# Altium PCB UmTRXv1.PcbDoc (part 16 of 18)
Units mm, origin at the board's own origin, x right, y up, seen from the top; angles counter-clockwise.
Board outline 172 x 113 mm, 6 copper layers (Top Layer, GND, MidLayer1, Mid-Layer 2, InternalPlane2, Bottom Layer); 766 components, 613 nets, 3008 pads, 1360 vias.
Unrouted connection lines stored in the file: 2.
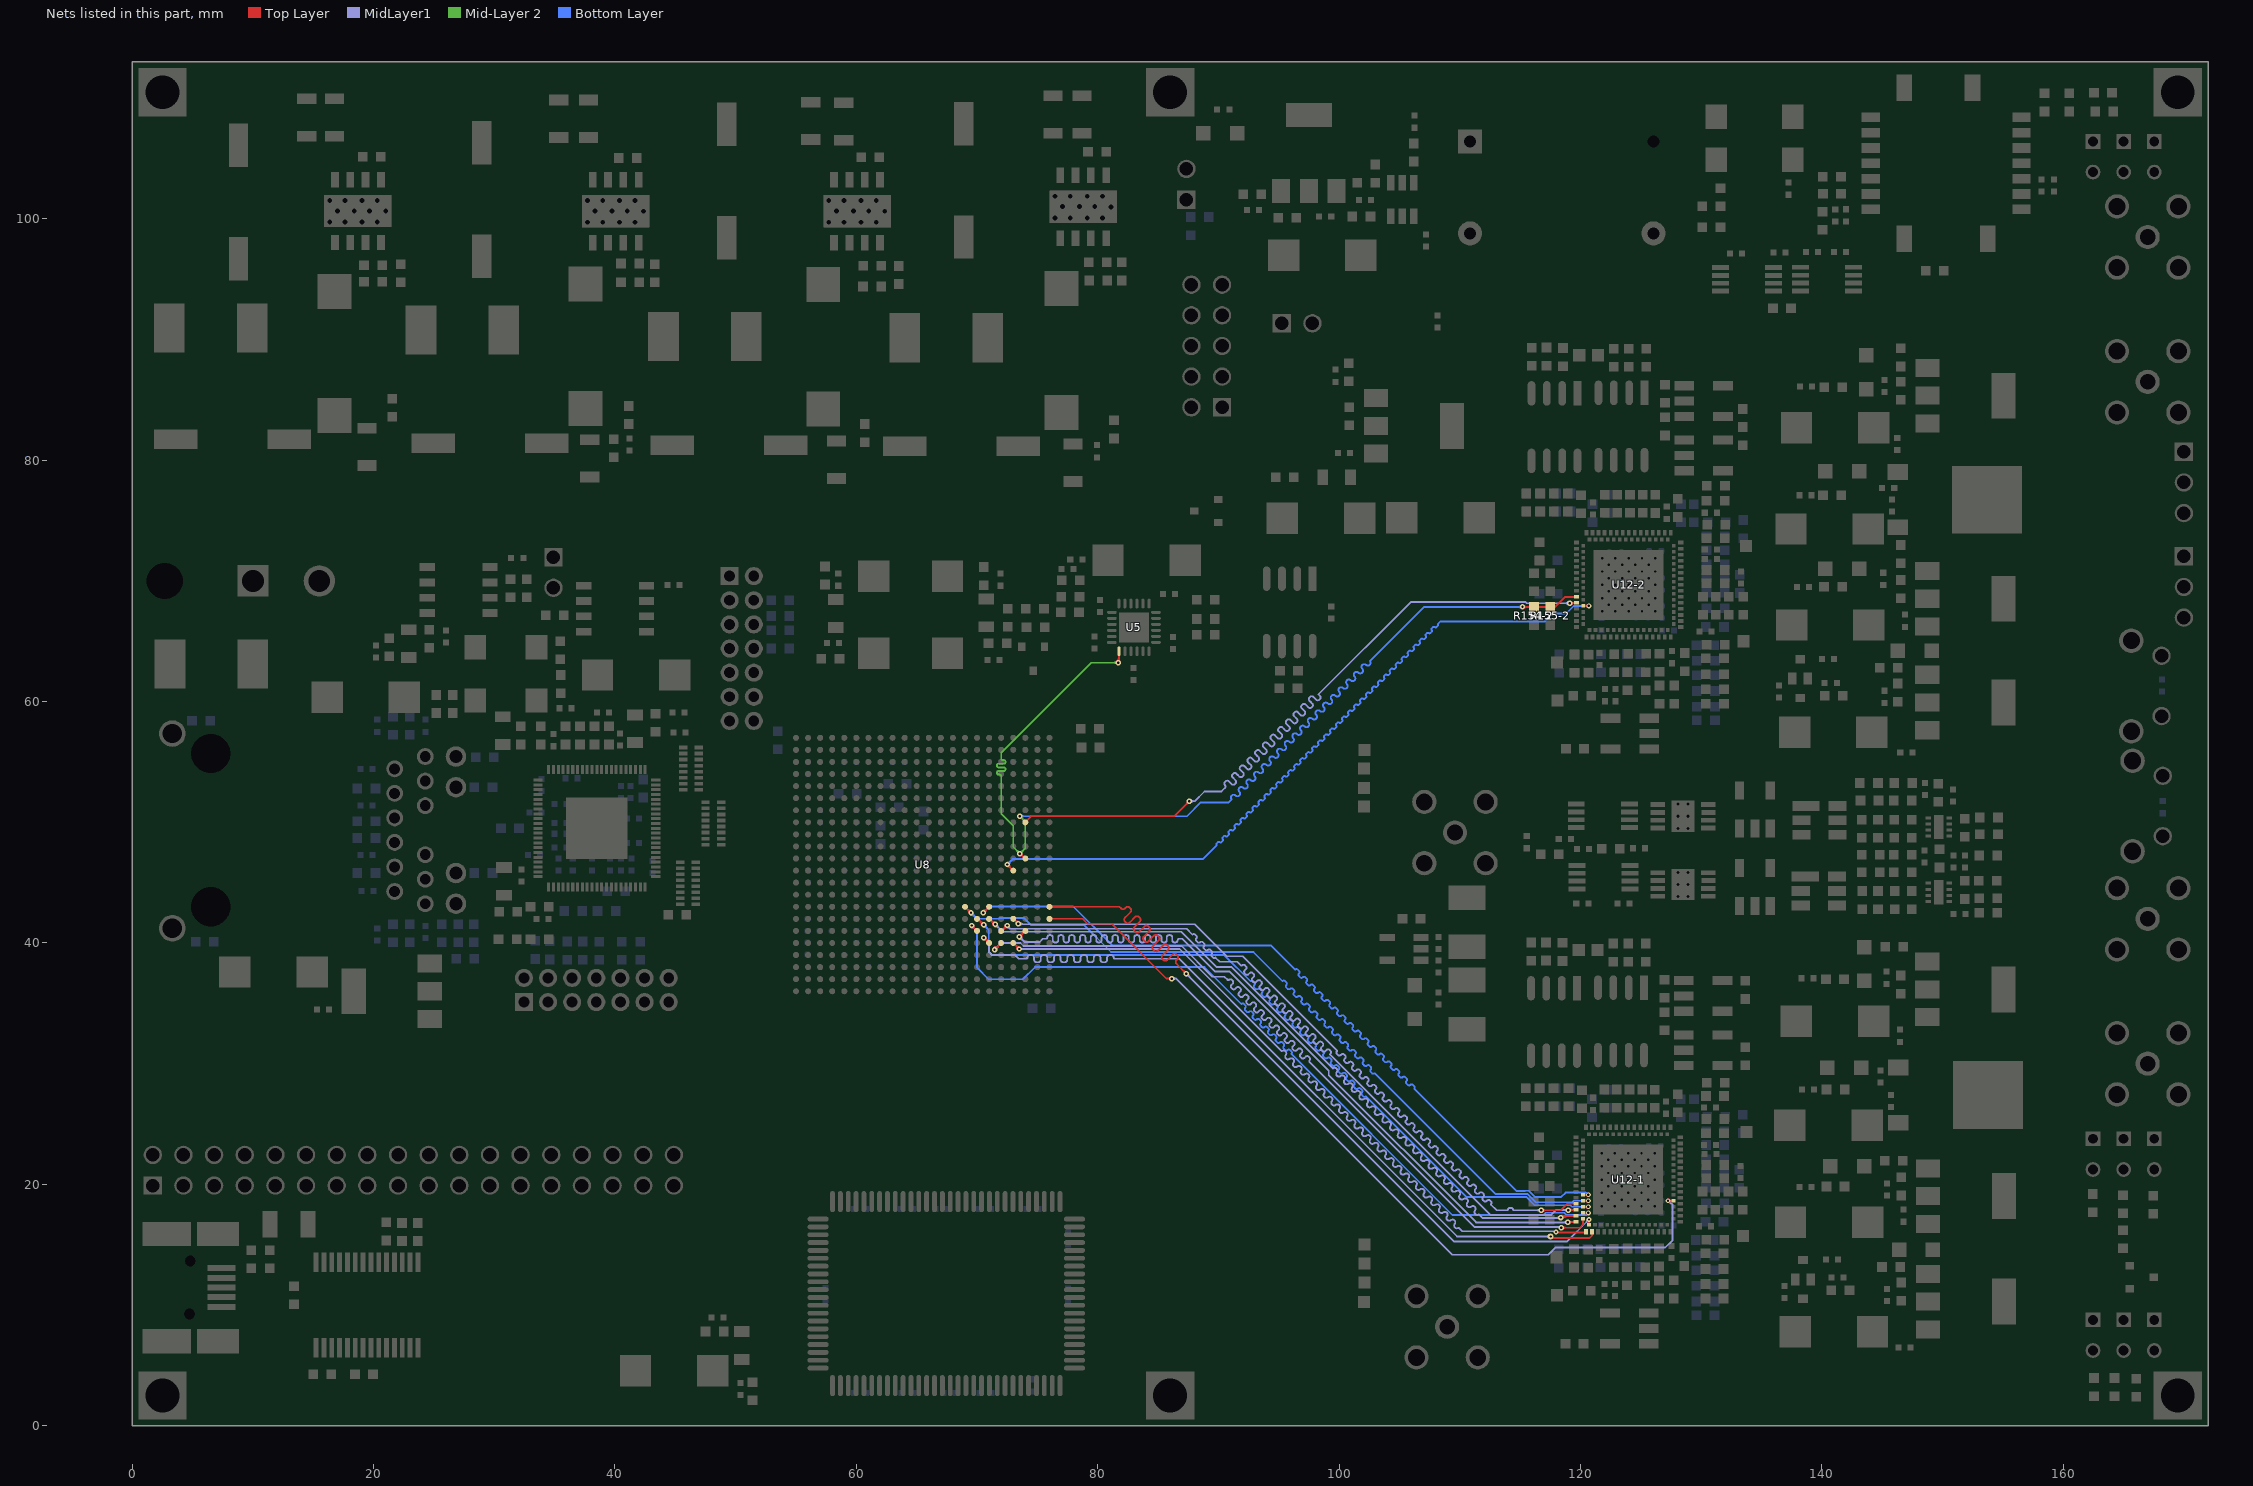
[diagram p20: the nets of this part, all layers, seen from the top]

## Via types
v1: diameter 0.45, hole 0.2, Top Layer to Bottom Layer, tented both sides, 554 vias
v2: diameter 0.5, hole 0.2, Top Layer to Bottom Layer, tented both sides, 468 vias
v3: diameter 0.7, hole 0.3, Top Layer to Bottom Layer, tented both sides, 206 vias
v4: diameter 0.4, hole 0.2, Top Layer to Bottom Layer, tented both sides, 82 vias
v5: diameter 0.8, hole 0.3, Top Layer to Bottom Layer, tented both sides, 16 vias
v6: diameter 0.6, hole 0.25, Top Layer to Bottom Layer, tented both sides, 16 vias
v7: diameter 0.5, hole 0.3, Top Layer to Bottom Layer, tented both sides, 8 vias
v8: diameter 0.7, hole 0.3, Top Layer to Bottom Layer, 4 vias
v9: diameter 0.6, hole 0.3, Top Layer to Bottom Layer, tented both sides, 4 vias
v10: diameter 0.5, hole 0.2, Top Layer to Bottom Layer, 2 vias

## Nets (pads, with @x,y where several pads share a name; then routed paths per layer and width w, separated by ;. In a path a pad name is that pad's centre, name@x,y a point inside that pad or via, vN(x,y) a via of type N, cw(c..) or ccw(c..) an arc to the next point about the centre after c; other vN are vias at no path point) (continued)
TX1D1: U8.H8 U12-1.22 | length 68.6
  Top Layer w0.15: U8.H8@69,43 v1(69.5,42.5) ; v1@69.325,42.5 ccw(c68.903,42.5) 69.201,42.799 ccw(c69.5,43.098) v1@69.5,42.675
  Top Layer w0.2: U12-1.22@120.207,18.638 v4@120.632,18.638 ; v4@120.586,18.567 ccw(c120.416,18.397) 120.416,18.638 ccw(c120.416,18.879) v4@120.586,18.709
  Bottom Layer w0.15: v1@69.5,42.325 cw(c69.5,41.903) 69.799,42.201 cw(c70.097,42.5) v1@69.675,42.5 ; v1(69.5,42.5) 70,42 71.8,42 71.875,42.075 73.875,42.075 74.45,41.5 78.85,41.5 81.1,39.25 92.9,39.25 95.309,36.841 cw(c95.415,36.735) 95.521,36.841 95.627,36.735 cw(c95.521,36.629) 95.627,36.523 ccw(c95.733,36.417) 95.627,36.311 95.733,36.205 ccw(c95.839,36.311) 95.945,36.205 cw(c96.052,36.098) 96.158,36.205 96.264,36.098 cw(c96.158,35.992) 96.264,35.886 ccw(c96.37,35.78) 96.264,35.674 96.37,35.568 ccw(c96.476,35.674) 96.582,35.568 cw(c96.688,35.462) 96.794,35.568 96.9,35.462 cw(c96.794,35.356) 96.9,35.25 ccw(c97.006,35.144) 96.9,35.038 97.006,34.932 ccw(c97.112,35.038) 97.218,34.932 cw(c97.324,34.826) 97.43,34.932 97.536,34.826 cw(c97.43,34.72) 97.536,34.614 ccw(c97.643,34.507) 97.536,34.401 97.643,34.295 ccw(c97.749,34.401) 97.855,34.295 cw(c97.961,34.189) 98.067,34.295 98.173,34.189 cw(c98.067,34.083) 98.173,33.977 ccw(c98.279,33.871) 98.173,33.765 98.279,33.659 ccw(c98.385,33.765) 98.491,33.659 cw(c98.597,33.553) 98.703,33.659 98.809,33.553 cw(c98.703,33.447) 98.809,33.341 ccw(c98.915,33.235) 98.809,33.129 98.915,33.023 ccw(c99.021,33.129) 99.127,33.023 cw(c99.234,32.916) 99.34,33.023 99.446,32.916 cw(c99.34,32.81) 99.446,32.704 ccw(c99.552,32.598) 99.446,32.492 99.552,32.386 ccw(c99.658,32.492) 99.764,32.386 cw(c99.87,32.28) 99.976,32.386 100.082,32.28 cw(c99.976,32.174) 100.082,32.068 ccw(c100.188,31.962) 100.082,31.856 100.188,31.75 ccw(c100.294,31.856) 100.4,31.75 cw(c100.506,31.644) 100.612,31.75 100.718,31.644 cw(c100.612,31.538) 100.718,31.432 ccw(c100.825,31.325) 100.718,31.219 100.825,31.113 ccw(c100.931,31.219) 101.037,31.113 cw(c101.143,31.007) 101.249,31.113 101.355,31.007 cw(c101.249,30.901) 101.355,30.795 ccw(c101.461,30.689) 101.355,30.583 101.461,30.477 ccw(c101.567,30.583) 101.673,30.477 cw(c101.779,30.371) 101.885,30.477 101.991,30.371 cw(c101.885,30.265) 101.991,30.159 ccw(c102.097,30.053) 101.991,29.947 102.097,29.841 ccw(c102.203,29.947) 102.309,29.841 cw(c102.416,29.734) 102.522,29.841 102.628,29.734 cw(c102.522,29.628) 102.628,29.522 ccw(c102.734,29.416) 102.628,29.31 102.734,29.204 ccw(c102.84,29.31) 102.946,29.204 112.942,19.208 115.53,19.208 115.544,19.222 115.596,19.222 116.298,18.52 119.31,18.52 119.428,18.638 v4(120.657,18.638) ; v4@120.569,18.55 ccw(c120.355,18.336) 120.355,18.638 ccw(c120.355,18.94) v4@120.569,18.726
TX1D2: U8.G4 U12-1.23 | length 69.6
  Top Layer w0.15: U8.G4@73,42 v1(73.4,41.6) ; v1@73.225,41.6 ccw(c72.802,41.6) 73.101,41.899 ccw(c73.4,42.197) v1@73.4,41.775 ; v1(116.75,17.85) 118.35,17.85 118.888,18.388 U12-1.23@119.632,18.388 ; v1@116.856,17.744 cw(c117.112,17.488) 117.112,17.85 cw(c117.112,18.212) v1@116.856,17.956 ; v1(73.4,41.6) 73.45,41.65 73.45,41.55 v1(73.4,41.6)
  MidLayer1 w0.15: v1@73.4,41.55 88.05,41.55 90.7,38.9 92,38.9 99.831,31.069 cw(c99.817,31.055) 99.831,31.041 ccw(c99.958,30.914) 99.831,30.786 99.894,30.723 ccw(c100.022,30.85) 100.149,30.723 100.163,30.737 100.177,30.751 cw(c100.304,30.624) 100.432,30.751 100.495,30.687 cw(c100.368,30.56) 100.495,30.433 100.481,30.419 100.467,30.405 ccw(c100.594,30.277) 100.467,30.15 100.531,30.086 ccw(c100.658,30.214) 100.785,30.086 100.799,30.101 100.814,30.115 cw(c100.941,29.987) 101.068,30.115 101.132,30.051 cw(c101.004,29.924) 101.132,29.797 101.118,29.782 101.103,29.768 ccw(c101.231,29.641) 101.103,29.514 101.167,29.45 ccw(c101.294,29.577) 101.422,29.45 101.436,29.464 101.45,29.478 cw(c101.577,29.351) 101.704,29.478 101.768,29.415 cw(c101.641,29.287) 101.768,29.16 101.74,29.132 ccw(c101.867,29.005) 101.74,28.877 101.803,28.814 ccw(c101.931,28.941) 102.058,28.814 102.072,28.828 102.086,28.842 cw(c102.214,28.715) 102.341,28.842 102.405,28.778 cw(c102.277,28.651) 102.405,28.524 102.39,28.51 102.376,28.495 ccw(c102.504,28.368) 102.376,28.241 102.44,28.177 ccw(c102.567,28.305) 102.694,28.177 102.709,28.191 102.723,28.206 cw(c102.85,28.078) 102.977,28.206 103.041,28.142 cw(c102.914,28.015) 103.041,27.887 103.027,27.873 103.013,27.859 ccw(c103.14,27.732) 103.013,27.605 103.076,27.541 ccw(c103.204,27.668) 103.331,27.541 103.345,27.555 103.359,27.569 cw(c103.486,27.442) 103.614,27.569 103.677,27.506 cw(c103.55,27.378) 103.677,27.251 103.663,27.237 103.649,27.223 ccw(c103.776,27.095) 103.649,26.968 103.713,26.904 ccw(c103.84,27.032) 103.967,26.904 103.996,26.933 cw(c104.123,26.805) 104.25,26.933 104.314,26.869 cw(c104.186,26.742) 104.314,26.615 104.3,26.6 104.285,26.586 ccw(c104.413,26.459) 104.285,26.332 104.349,26.268 ccw(c104.476,26.395) 104.604,26.268 104.618,26.282 104.632,26.296 cw(c104.759,26.169) 104.886,26.296 104.95,26.233 cw(c104.823,26.105) 104.95,25.978 104.936,25.964 104.922,25.95 ccw(c105.049,25.823) 104.922,25.695 104.985,25.632 ccw(c105.113,25.759) 105.24,25.632 105.254,25.646 105.268,25.66 cw(c105.396,25.533) 105.523,25.66 105.587,25.596 cw(c105.459,25.469) 105.587,25.342 105.572,25.328 105.558,25.313 ccw(c105.685,25.186) 105.558,25.059 105.622,24.995 ccw(c105.749,25.123) 105.876,24.995 105.891,25.009 105.905,25.024 cw(c106.032,24.896) 106.159,25.024 106.223,24.96 cw(c106.096,24.833) 106.223,24.705 106.209,24.691 106.195,24.677 ccw(c106.322,24.55) 106.195,24.423 106.258,24.359 ccw(c106.386,24.486) 106.513,24.359 106.527,24.373 106.541,24.387 cw(c106.668,24.26) 106.796,24.387 106.859,24.324 cw(c106.732,24.196) 106.859,24.069 106.845,24.055 106.831,24.041 ccw(c106.958,23.913) 106.831,23.786 106.895,23.723 ccw(c107.022,23.85) 107.149,23.723 107.163,23.737 107.177,23.751 cw(c107.305,23.624) 107.432,23.751 107.496,23.687 cw(c107.368,23.56) 107.496,23.433 107.482,23.418 107.467,23.404 ccw(c107.595,23.277) 107.467,23.15 107.531,23.086 ccw(c107.658,23.213) 107.786,23.086 107.8,23.1 107.814,23.114 cw(c107.941,22.987) 108.068,23.114 108.132,23.051 cw(c108.005,22.923) 108.132,22.796 108.118,22.782 108.104,22.768 ccw(c108.231,22.641) 108.104,22.513 108.167,22.45 ccw(c108.295,22.577) 108.422,22.45 108.436,22.464 108.45,22.478 cw(c108.578,22.351) 108.705,22.478 108.768,22.414 cw(c108.641,22.287) 108.768,22.16 108.754,22.146 108.74,22.132 ccw(c108.867,22.004) 108.74,21.877 108.804,21.813 ccw(c108.931,21.941) 109.058,21.813 109.073,21.827 109.087,21.842 cw(c109.214,21.714) 109.341,21.842 109.405,21.778 cw(c109.278,21.651) 109.405,21.523 109.391,21.509 109.377,21.495 ccw(c109.504,21.368) 109.377,21.241 109.44,21.177 ccw(c109.568,21.304) 109.695,21.177 109.709,21.191 109.723,21.205 cw(c109.85,21.078) 109.978,21.205 110.041,21.142 cw(c109.914,21.014) 110.041,20.887 110.027,20.873 110.013,20.859 ccw(c110.14,20.731) 110.013,20.604 110.077,20.541 ccw(c110.204,20.668) 110.331,20.541 110.345,20.555 110.359,20.569 cw(c110.487,20.442) 110.614,20.569 110.678,20.505 cw(c110.55,20.378) 110.678,20.251 110.664,20.236 110.649,20.222 ccw(c110.777,20.095) 110.649,19.968 110.713,19.904 ccw(c110.84,20.031) 110.968,19.904 110.982,19.918 110.996,19.932 cw(c111.123,19.805) 111.25,19.932 111.314,19.869 cw(c111.187,19.742) 111.314,19.614 111.3,19.6 111.286,19.586 ccw(c111.413,19.459) 111.286,19.331 111.349,19.268 ccw(c111.477,19.395) 111.604,19.268 111.618,19.282 111.632,19.296 cw(c111.76,19.169) 111.887,19.296 111.95,19.232 cw(c111.823,19.105) 111.95,18.978 111.936,18.964 111.922,18.95 ccw(c112.049,18.822) 111.922,18.695 111.986,18.631 ccw(c112.113,18.759) 112.24,18.631 112.255,18.645 112.269,18.66 cw(c112.396,18.532) 112.523,18.66 112.587,18.596 cw(c112.46,18.469) 112.587,18.341 ccw(c112.601,18.327) 112.587,18.313 113.05,17.85 113.955,17.85 ccw(c113.955,17.87) 113.975,17.87 cw(c114.155,17.87) 114.155,18.05 114.245,18.05 cw(c114.245,17.87) 114.425,17.87 ccw(c114.445,17.87) 114.445,17.85 v1(116.75,17.85) ; v1@73.524,41.476 cw(c73.702,41.298) 73.702,41.55 ; v1@73.524,41.724 ccw(c73.943,42.143) 73.943,41.55 ; v1@116.644,17.744 ccw(c116.388,17.488) 116.388,17.85 ccw(c116.388,18.212) v1@116.644,17.956
TX1D3: U8.G7 U12-1.24 | length 69.3
  Top Layer w0.15: U8.G7@70,42 70.05,42 v1(70.55,41.5) ; v1@70.375,41.5 ccw(c69.953,41.5) 70.251,41.799 ccw(c70.55,42.097) v1@70.55,41.675
  Top Layer w0.2: U12-1.24@120.207,18.138 v4@120.632,18.138 ; v4@120.586,18.067 ccw(c120.416,17.897) 120.416,18.138 ccw(c120.416,18.379) v4@120.586,18.209
  Bottom Layer w0.15: v1@70.55,41.325 cw(c70.55,40.903) 70.849,41.201 cw(c71.147,41.5) v1@70.725,41.5 ; v1(70.55,41.5) 70.975,41.075 70.975,39.275 71.25,39 90.5,39 92.659,36.841 cw(c92.765,36.735) 92.871,36.841 92.977,36.735 cw(c92.871,36.629) 92.977,36.523 ccw(c93.083,36.417) 92.977,36.311 93.083,36.205 ccw(c93.189,36.311) 93.295,36.205 cw(c93.402,36.098) 93.508,36.205 93.614,36.098 cw(c93.508,35.992) 93.614,35.886 ccw(c93.72,35.78) 93.614,35.674 93.72,35.568 ccw(c93.826,35.674) 93.932,35.568 cw(c94.038,35.462) 94.144,35.568 94.25,35.462 cw(c94.144,35.356) 94.25,35.25 ccw(c94.356,35.144) 94.25,35.038 94.356,34.932 ccw(c94.462,35.038) 94.568,34.932 cw(c94.674,34.826) 94.78,34.932 94.886,34.826 cw(c94.78,34.72) 94.886,34.614 ccw(c94.993,34.507) 94.886,34.401 94.993,34.295 ccw(c95.099,34.401) 95.205,34.295 cw(c95.311,34.189) 95.417,34.295 95.523,34.189 cw(c95.417,34.083) 95.523,33.977 ccw(c95.629,33.871) 95.523,33.765 95.629,33.659 ccw(c95.735,33.765) 95.841,33.659 cw(c95.947,33.553) 96.053,33.659 96.159,33.553 cw(c96.053,33.447) 96.159,33.341 ccw(c96.265,33.235) 96.159,33.129 96.265,33.023 ccw(c96.371,33.129) 96.477,33.023 cw(c96.584,32.916) 96.69,33.023 96.796,32.916 cw(c96.69,32.81) 96.796,32.704 ccw(c96.902,32.598) 96.796,32.492 96.902,32.386 ccw(c97.008,32.492) 97.114,32.386 cw(c97.22,32.28) 97.326,32.386 97.432,32.28 cw(c97.326,32.174) 97.432,32.068 ccw(c97.538,31.962) 97.432,31.856 97.538,31.75 ccw(c97.644,31.856) 97.75,31.75 cw(c97.856,31.644) 97.962,31.75 98.068,31.644 cw(c97.962,31.538) 98.068,31.432 ccw(c98.175,31.325) 98.068,31.219 98.175,31.113 ccw(c98.281,31.219) 98.387,31.113 cw(c98.493,31.007) 98.599,31.113 98.705,31.007 cw(c98.599,30.901) 98.705,30.795 ccw(c98.811,30.689) 98.705,30.583 98.811,30.477 ccw(c98.917,30.583) 99.023,30.477 cw(c99.129,30.371) 99.235,30.477 99.341,30.371 cw(c99.235,30.265) 99.341,30.159 ccw(c99.447,30.053) 99.341,29.947 99.447,29.841 ccw(c99.553,29.947) 99.659,29.841 cw(c99.766,29.734) 99.872,29.841 99.978,29.734 cw(c99.872,29.628) 99.978,29.522 ccw(c100.084,29.416) 99.978,29.31 100.084,29.204 ccw(c100.19,29.31) 100.296,29.204 cw(c100.402,29.098) 100.508,29.204 100.614,29.098 cw(c100.508,28.992) 100.614,28.886 ccw(c100.72,28.78) 100.614,28.674 100.72,28.568 ccw(c100.826,28.674) 100.932,28.568 cw(c101.038,28.462) 101.144,28.568 101.25,28.462 cw(c101.144,28.356) 101.25,28.25 ccw(c101.356,28.144) 101.25,28.037 101.356,27.931 ccw(c101.463,28.037) 101.569,27.931 cw(c101.675,27.825) 101.781,27.931 101.887,27.825 cw(c101.781,27.719) 101.887,27.613 ccw(c101.993,27.507) 101.887,27.401 101.993,27.295 ccw(c102.099,27.401) 102.205,27.295 110.542,18.958 115.506,18.958 116.194,18.27 119.165,18.27 119.297,18.138 v4(120.657,18.138) ; v4@120.569,18.05 ccw(c120.355,17.836) 120.355,18.138 ccw(c120.355,18.44) v4@120.569,18.226
TX1D4: U8.F5 U12-1.25 | length 69.3
  Top Layer w0.15: U8.F5@72,41 72.05,41 v1(72.5,41.45) v1@72.55,41.5 ; v1@72.325,41.45 cw(c71.903,41.45) 72.201,41.151 cw(c72.5,40.853) v1@72.5,41.275 ; v1(118.999,17.87) 118.981,17.888 U12-1.25@119.632,17.888 ; v1@119.105,17.764 cw(c119.404,17.465) 119.404,17.888 ; v1@119.105,17.976 ccw(c119.318,18.189) 119.318,17.888
  MidLayer1 w0.15: v1@72.5,41.275 cw(c72.5,40.973) 72.713,41.187 ; v1@72.55,41.5 72.55,41.35 72.725,41.175 ; v1@72.668,41.4 ccw(c72.886,41.336) 72.725,41.175 ; 98.641,31.458 98.542,31.359 ccw(c98.669,31.232) 98.542,31.105 98.605,31.041 ccw(c98.733,31.168) 98.86,31.041 98.909,31.091 98.959,31.14 cw(c99.086,31.013) 99.213,31.14 99.277,31.076 cw(c99.15,30.949) 99.277,30.822 ccw(c99.327,30.772) 99.277,30.723 112.55,17.45 117.55,17.45 117.97,17.87 v1(118.999,17.87) ; 98.641,31.458 ccw(c98.513,31.586) 98.641,31.713 98.577,31.776 ccw(c98.45,31.649) 98.323,31.776 98.273,31.727 98.224,31.677 cw(c98.096,31.805) 97.969,31.677 97.905,31.741 cw(c98.033,31.868) 97.905,31.996 98.004,32.095 ccw(c97.877,32.222) 98.004,32.349 97.941,32.413 ccw(c97.813,32.286) 97.686,32.413 97.587,32.314 cw(c97.46,32.441) 97.333,32.314 97.269,32.377 cw(c97.396,32.505) 97.269,32.632 97.368,32.731 ccw(c97.241,32.858) 97.368,32.986 97.304,33.049 ccw(c97.177,32.922) 97.05,33.049 96.951,32.95 cw(c96.823,33.078) 96.696,32.95 96.633,33.014 cw(c96.76,33.141) 96.633,33.268 96.682,33.318 96.732,33.367 ccw(c96.604,33.495) 96.732,33.622 96.668,33.686 ccw(c96.541,33.558) 96.413,33.686 96.314,33.587 cw(c96.187,33.714) 96.06,33.587 95.996,33.65 cw(c96.123,33.778) 95.996,33.905 96.046,33.954 96.095,34.004 ccw(c95.968,34.131) 96.095,34.258 96.032,34.322 ccw(c95.904,34.195) 95.777,34.322 95.678,34.223 cw(c95.551,34.35) 95.423,34.223 95.36,34.287 cw(c95.487,34.414) 95.36,34.541 95.459,34.64 ccw(c95.331,34.768) 95.459,34.895 95.395,34.958 ccw(c95.268,34.831) 95.141,34.958 95.042,34.859 cw(c94.914,34.987) 94.787,34.859 94.723,34.923 cw(c94.851,35.05) 94.723,35.178 94.822,35.277 ccw(c94.695,35.404) 94.822,35.531 94.759,35.595 ccw(c94.631,35.468) 94.504,35.595 94.455,35.545 94.405,35.496 cw(c94.278,35.623) 94.151,35.496 94.087,35.559 cw(c94.214,35.687) 94.087,35.814 94.186,35.913 ccw(c94.059,36.04) 94.186,36.168 94.122,36.231 ccw(c93.995,36.104) 93.868,36.231 93.818,36.182 93.769,36.132 cw(c93.642,36.26) 93.514,36.132 93.451,36.196 cw(c93.578,36.323) 93.451,36.45 93.55,36.549 ccw(c93.422,36.677) 93.55,36.804 93.486,36.868 ccw(c93.359,36.74) 93.231,36.868 93.132,36.769 cw(c93.005,36.896) 92.878,36.769 92.814,36.832 cw(c92.941,36.96) 92.814,37.087 92.913,37.186 ccw(c92.786,37.313) 92.913,37.44 92.85,37.504 ccw(c92.722,37.377) 92.595,37.504 92.496,37.405 cw(c92.369,37.532) 92.241,37.405 92.178,37.469 cw(c92.305,37.596) 92.178,37.723 92.227,37.773 92.277,37.822 ccw(c92.15,37.949) 92.277,38.077 92.213,38.14 ccw(c92.086,38.013) 91.959,38.14 cw(c91.909,38.19) 91.86,38.14 91.55,38.45 90.1,38.45 89.762,38.788 cw(c89.655,38.895) 89.549,38.788 89.443,38.895 cw(c89.549,39.001) 89.443,39.107 ccw(c89.337,39.213) 89.443,39.319 89.337,39.425 ccw(c89.231,39.319) 89.125,39.425 cw(c89.019,39.531) 88.913,39.425 88.807,39.531 cw(c88.913,39.637) 88.807,39.743 ccw(c88.701,39.849) 88.807,39.955 88.701,40.061 ccw(c88.595,39.955) 88.489,40.061 cw(c88.383,40.167) 88.277,40.061 88.171,40.167 cw(c88.277,40.273) 88.171,40.379 ccw(c88.064,40.486) 88.171,40.592 88.064,40.698 ccw(c87.958,40.592) 87.852,40.698 87.375,41.175 74.78,41.175 74.22,41.175 72.78,41.175 72.725,41.175 ; v1@118.893,17.764 ccw(c118.637,17.508) 118.637,17.87 ccw(c118.637,18.232) v1@118.893,17.976
TX1D5: U8.F7 U12-1.26 | length 70
  Top Layer w0.15: v1@69.55,41.275 cw(c69.55,40.853) 69.849,41.151 cw(c70.148,41.45) v1@69.725,41.45 ; v1(69.55,41.45) U8.F7@70,41
  Top Layer w0.2: U12-1.26@120.207,17.638 v4@120.632,17.638 ; v4@120.586,17.567 ccw(c120.416,17.397) 120.416,17.638 ccw(c120.416,17.879) v4@120.586,17.709
  Bottom Layer w0.15: v1@69.55,41.275 cw(c69.55,40.853) 69.849,41.151 cw(c70.147,41.45) v1@69.725,41.45 ; v1(69.55,41.45) 70,41 70,37.95 70.95,37 73.8,37 74.8,38 88.85,38 91.909,34.941 cw(c92.015,34.835) 92.121,34.941 92.227,34.835 cw(c92.121,34.729) 92.227,34.623 ccw(c92.333,34.517) 92.227,34.411 92.333,34.305 ccw(c92.439,34.411) 92.545,34.305 cw(c92.652,34.198) 92.758,34.305 92.864,34.198 cw(c92.758,34.092) 92.864,33.986 ccw(c92.97,33.88) 92.864,33.774 92.97,33.668 ccw(c93.076,33.774) 93.182,33.668 cw(c93.288,33.562) 93.394,33.668 93.5,33.562 cw(c93.394,33.456) 93.5,33.35 ccw(c93.606,33.244) 93.5,33.138 93.606,33.032 ccw(c93.712,33.138) 93.818,33.032 cw(c93.924,32.926) 94.03,33.032 94.136,32.926 cw(c94.03,32.82) 94.136,32.714 ccw(c94.243,32.607) 94.136,32.501 94.243,32.395 ccw(c94.349,32.501) 94.455,32.395 cw(c94.561,32.289) 94.667,32.395 94.773,32.289 cw(c94.667,32.183) 94.773,32.077 ccw(c94.879,31.971) 94.773,31.865 94.879,31.759 ccw(c94.985,31.865) 95.091,31.759 cw(c95.197,31.653) 95.303,31.759 95.409,31.653 cw(c95.303,31.547) 95.409,31.441 ccw(c95.515,31.335) 95.409,31.229 95.515,31.123 ccw(c95.621,31.229) 95.727,31.123 cw(c95.834,31.016) 95.94,31.123 96.046,31.016 cw(c95.94,30.91) 96.046,30.804 109.4,17.45 116.916,17.45 117.115,17.649 118.655,17.649 118.833,17.47 120.489,17.47 v4(120.657,17.638) ; 119.95,17.47 ccw(c119.95,18.345) v4@120.569,17.726 ; 120.312,17.47 ccw(c120.312,17.983) v4@120.675,17.62
TX1D6: U8.G6 U12-1.27 | length 69.9
  Top Layer w0.15: U8.G6@71,42 71.45,41.55 v1(71.5,41.55) ; U8.G6@71.116,41.884 ccw(c71.5,42.268) v1@71.5,41.725 ; 71.237,41.763 cw(c71.023,41.55) v1@71.325,41.55 ; v1@118.481,17.143 cw(c119.072,16.551) 119.072,17.388 ; 118.71,17.388 ccw(c118.71,16.913) v1(118.375,17.249) 118.461,17.408 118.441,17.388 U12-1.27@119.632,17.388
  MidLayer1 w0.15: v1@71.5,41.375 cw(c71.5,40.953) 71.799,41.251 cw(c72.097,41.55) v1@71.675,41.55 ; v1(71.5,41.55) 72.1,40.95 72.1,40.925 72.324,40.925 72.676,40.925 74.324,40.925 74.676,40.925 86.925,40.925 89.85,38 91.1,38 99.49,29.61 cw(c99.631,29.432) 99.809,29.291 ccw(c99.986,29.151) 100.127,28.973 cw(c100.267,28.795) 100.445,28.655 ccw(c100.623,28.515) 100.763,28.337 cw(c100.903,28.159) 101.081,28.019 ccw(c101.259,27.878) 101.399,27.701 cw(c101.54,27.523) 101.718,27.382 ccw(c101.896,27.242) 102.036,27.064 cw(c102.176,26.886) 102.354,26.746 ccw(c102.532,26.606) 102.672,26.428 cw(c102.813,26.25) 102.99,26.11 ccw(c103.168,25.969) 103.309,25.791 cw(c103.449,25.613) 103.627,25.473 ccw(c103.805,25.333) 103.945,25.155 cw(c104.085,24.977) 104.263,24.837 ccw(c104.441,24.696) 104.581,24.519 cw(c104.722,24.341) 104.9,24.2 ccw(c105.078,24.06) 105.218,23.882 cw(c105.358,23.704) 105.536,23.564 ccw(c105.714,23.424) 105.854,23.246 cw(c105.995,23.068) 106.172,22.928 ccw(c106.35,22.787) 106.491,22.609 cw(c106.631,22.431) 106.809,22.291 ccw(c106.987,22.151) 107.127,21.973 cw(c107.267,21.795) 107.445,21.655 ccw(c107.623,21.514) 107.763,21.337 cw(c107.904,21.159) 108.082,21.018 ccw(c108.26,20.878) 108.4,20.7 cw(c108.54,20.522) 108.718,20.382 ccw(c108.896,20.242) 109.036,20.064 cw(c109.177,19.886) 109.354,19.746 ccw(c109.532,19.605) 109.673,19.427 cw(c109.813,19.249) 109.991,19.109 ccw(c110.169,18.969) 110.309,18.791 cw(c110.449,18.613) 110.627,18.473 ccw(c110.805,18.332) 110.945,18.155 cw(c111.086,17.977) 111.264,17.836 ccw(c111.441,17.696) 111.582,17.518 111.9,17.2 118.326,17.2 v1(118.375,17.249) ; 117.894,17.2 ccw(c117.894,17.729) v1@118.268,17.355 ; 118.131,17.2 cw(c118.131,17.005) v1@118.268,17.143
TX1D7: U8.E5 U12-1.28 | length 69.2
  Top Layer w0.15: v1(71.45,39.45) U8.E5@72,40 ; v1@71.45,39.625 ccw(c71.45,40.047) 71.749,39.749 ccw(c72.047,39.45) v1@71.625,39.45 ; v1(118.411,16.408) 119.977,16.408 120.207,16.638 U12-1.28@120.207,17.138 ; v1@118.517,16.302 cw(c118.773,16.046) 118.773,16.408 cw(c118.773,16.77) v1@118.517,16.514
  MidLayer1 w0.15: v1(71.45,39.45) 72,40 73.601,40 73.851,39.751 ; v1@71.45,39.625 ccw(c71.45,40.047) 71.749,39.749 ccw(c72.047,39.45) v1@71.625,39.45 ; 73.85,39.75 86.95,39.75 89.5,37.2 90.5,37.2 90.76,36.94 ccw(c90.809,36.99) 90.859,36.94 cw(c90.986,36.813) 91.113,36.94 91.177,36.877 cw(c91.05,36.749) 91.177,36.622 91.127,36.573 91.078,36.523 ccw(c91.205,36.396) 91.078,36.269 91.141,36.205 ccw(c91.269,36.332) 91.396,36.205 91.495,36.304 cw(c91.622,36.177) 91.75,36.304 91.813,36.24 cw(c91.686,36.113) 91.813,35.986 91.714,35.887 ccw(c91.841,35.76) 91.714,35.632 91.778,35.569 ccw(c91.905,35.696) 92.032,35.569 92.131,35.668 cw(c92.259,35.54) 92.386,35.668 92.45,35.604 cw(c92.322,35.477) 92.45,35.349 92.351,35.25 ccw(c92.478,35.123) 92.351,34.996 92.414,34.932 ccw(c92.542,35.059) 92.669,34.932 92.718,34.982 92.768,35.031 cw(c92.895,34.904) 93.022,35.031 93.086,34.968 cw(c92.959,34.84) 93.086,34.713 92.987,34.614 ccw(c93.114,34.487) 92.987,34.359 93.051,34.296 ccw(c93.178,34.423) 93.305,34.296 93.355,34.345 93.404,34.395 cw(c93.531,34.268) 93.659,34.395 93.722,34.331 cw(c93.595,34.204) 93.722,34.077 93.623,33.978 ccw(c93.751,33.85) 93.623,33.723 93.687,33.659 ccw(c93.814,33.787) 93.942,33.659 94.041,33.758 cw(c94.168,33.631) 94.295,33.758 94.359,33.695 cw(c94.231,33.568) 94.359,33.44 94.26,33.341 ccw(c94.387,33.214) 94.26,33.087 94.323,33.023 ccw(c94.451,33.15) 94.578,33.023 94.677,33.122 cw(c94.804,32.995) 94.932,33.122 94.995,33.058 cw(c94.868,32.931) 94.995,32.804 94.946,32.754 94.896,32.705 ccw(c95.023,32.578) 94.896,32.45 94.96,32.387 ccw(c95.087,32.514) 95.214,32.387 95.313,32.486 cw(c95.441,32.358) 95.568,32.486 95.632,32.422 cw(c95.504,32.295) 95.632,32.167 95.582,32.118 95.533,32.068 ccw(c95.66,31.941) 95.533,31.814 95.596,31.75 ccw(c95.723,31.878) 95.851,31.75 95.95,31.849 cw(c96.077,31.722) 96.204,31.849 96.268,31.786 cw(c96.141,31.658) 96.268,31.531 96.169,31.432 ccw(c96.296,31.305) 96.169,31.177 96.233,31.114 ccw(c96.36,31.241) 96.487,31.114 96.586,31.213 cw(c96.713,31.086) 96.841,31.213 96.904,31.149 cw(c96.777,31.022) 96.904,30.895 96.805,30.796 ccw(c96.933,30.668) 96.805,30.541 96.869,30.477 ccw(c96.996,30.605) 97.124,30.477 97.173,30.527 97.223,30.576 cw(c97.35,30.449) 97.477,30.576 97.541,30.513 cw(c97.413,30.386) 97.541,30.258 ccw(c97.59,30.209) 97.541,30.159 111.247,16.453 118.366,16.453 v1(118.411,16.408)
TX1D8: U8.F3 U12-1.29 | length 70.1
  Top Layer w0.15: v1(73.5,40.5) U8.F3@74,41 ; v1@73.5,40.675 ccw(c73.5,41.097) 73.799,40.799 ccw(c74.098,40.5) v1@73.675,40.5 ; v1(118.961,16.858) 118.991,16.888 U12-1.29@119.632,16.888 ; v1@119.067,16.752 cw(c119.395,16.424) 119.395,16.888 ; v1@119.067,16.964 ccw(c119.251,17.148) 119.251,16.888
  MidLayer1 w0.15: v1@73.5,40.325 cw(c73.5,39.793) 73.876,40.169 ; v1(73.5,40.5) 73.545,40.5 73.97,40.075 75.175,40.075 75.45,40.35 75.705,40.35 ccw(c75.705,40.47) 75.825,40.47 cw(c76.005,40.47) 76.005,40.65 76.095,40.65 cw(c76.095,40.47) 76.275,40.47 76.275,40.23 ccw(c76.455,40.23) 76.455,40.05 76.545,40.05 ccw(c76.545,40.23) 76.725,40.23 76.725,40.47 cw(c76.905,40.47) 76.905,40.65 76.995,40.65 cw(c76.995,40.47) 77.175,40.47 77.175,40.23 ccw(c77.355,40.23) 77.355,40.05 77.445,40.05 ccw(c77.445,40.23) 77.625,40.23 77.625,40.47 cw(c77.805,40.47) 77.805,40.65 77.895,40.65 cw(c77.895,40.47) 78.075,40.47 78.075,40.23 ccw(c78.255,40.23) 78.255,40.05 78.345,40.05 ccw(c78.345,40.23) 78.525,40.23 78.525,40.47 cw(c78.705,40.47) 78.705,40.65 78.795,40.65 cw(c78.795,40.47) 78.975,40.47 78.975,40.23 ccw(c79.155,40.23) 79.155,40.05 79.245,40.05 ccw(c79.245,40.23) 79.425,40.23 79.425,40.47 cw(c79.605,40.47) 79.605,40.65 79.695,40.65 cw(c79.695,40.47) 79.875,40.47 79.875,40.23 ccw(c80.055,40.23) 80.055,40.05 80.145,40.05 ccw(c80.145,40.23) 80.325,40.23 80.325,40.47 cw(c80.505,40.47) 80.505,40.65 80.595,40.65 cw(c80.595,40.47) 80.775,40.47 80.775,40.23 ccw(c80.955,40.23) 80.955,40.05 81.045,40.05 ccw(c81.045,40.23) 81.225,40.23 81.225,40.47 cw(c81.405,40.47) 81.405,40.65 81.495,40.65 cw(c81.495,40.47) 81.675,40.47 81.675,40.23 ccw(c81.855,40.23) 81.855,40.05 81.945,40.05 ccw(c81.945,40.23) 82.125,40.23 82.125,40.47 cw(c82.305,40.47) 82.305,40.65 82.395,40.65 cw(c82.395,40.47) 82.575,40.47 82.575,40.23 ccw(c82.755,40.23) 82.755,40.05 82.845,40.05 ccw(c82.845,40.23) 83.025,40.23 83.025,40.47 cw(c83.205,40.47) 83.205,40.65 83.295,40.65 cw(c83.295,40.47) 83.475,40.47 83.475,40.23 ccw(c83.655,40.23) 83.655,40.05 83.745,40.05 ccw(c83.745,40.23) 83.925,40.23 83.925,40.47 cw(c84.105,40.47) 84.105,40.65 84.195,40.65 cw(c84.195,40.47) 84.375,40.47 84.375,40.23 ccw(c84.555,40.23) 84.555,40.05 84.645,40.05 ccw(c84.645,40.23) 84.825,40.23 84.825,40.47 cw(c85.005,40.47) 85.005,40.65 85.095,40.65 cw(c85.095,40.47) 85.275,40.47 85.275,40.23 ccw(c85.455,40.23) 85.455,40.05 85.545,40.05 ccw(c85.545,40.23) 85.725,40.23 85.725,40.47 cw(c85.905,40.47) 85.905,40.65 85.995,40.65 cw(c85.995,40.47) 86.175,40.47 86.175,40.23 ccw(c86.355,40.23) 86.355,40.05 86.445,40.05 ccw(c86.445,40.23) 86.625,40.23 cw(c86.745,40.23) 86.745,40.35 87,40.35 89.725,37.625 90.925,37.625 99.15,29.4 99.15,29.05 111.351,16.849 118.952,16.849 v1(118.961,16.858) ; v1@73.675,40.5 ccw(c73.988,40.5) 73.767,40.279 ; 118.577,16.849 ccw(c118.577,17.243) v1@118.855,16.964 ; 118.621,16.849 cw(c118.621,16.518) v1@118.855,16.752
TX1D9: U8.E4 U12-1.30 | length 67.7
  Top Layer w0.15: U8.E4@73,40 v1(73.5,39.5) ; v1@73.325,39.5 ccw(c72.903,39.5) 73.201,39.799 ccw(c73.5,40.097) v1@73.5,39.675 ; v1(117.974,16.053) 118.02,16.008 120.402,16.008 U12-1.30@120.457,16.063
  MidLayer1 w0.15: v1(73.5,39.5) 86.8,39.5 95.263,31.037 cw(c95.403,30.859) 95.581,30.719 ccw(c95.759,30.579) 95.899,30.401 cw(c96.04,30.223) 96.218,30.082 ccw(c96.395,29.942) 96.536,29.764 cw(c96.676,29.586) 96.854,29.446 ccw(c97.032,29.306) 97.172,29.128 cw(c97.312,28.95) 97.49,28.81 ccw(c97.668,28.669) 97.808,28.492 cw(c97.949,28.314) 98.127,28.173 ccw(c98.305,28.033) 98.445,27.855 cw(c98.585,27.677) 98.763,27.537 ccw(c98.941,27.397) 99.081,27.219 cw(c99.222,27.041) 99.399,26.901 ccw(c99.577,26.76) 99.718,26.582 cw(c99.858,26.404) 100.036,26.264 ccw(c100.214,26.124) 100.354,25.946 cw(c100.494,25.768) 100.672,25.628 ccw(c100.85,25.487) 100.99,25.31 cw(c101.131,25.132) 101.309,24.991 ccw(c101.487,24.851) 101.627,24.673 cw(c101.767,24.495) 101.945,24.355 ccw(c102.123,24.215) 102.263,24.037 cw(c102.404,23.859) 102.581,23.719 ccw(c102.759,23.578) 102.9,23.4 cw(c103.04,23.222) 103.218,23.082 ccw(c103.396,22.942) 103.536,22.764 cw(c103.676,22.586) 103.854,22.446 ccw(c104.032,22.305) 104.172,22.128 cw(c104.313,21.95) 104.491,21.809 ccw(c104.669,21.669) 104.809,21.491 cw(c104.949,21.313) 105.127,21.173 ccw(c105.305,21.033) 105.445,20.855 cw(c105.586,20.677) 105.763,20.537 ccw(c105.941,20.396) 106.082,20.218 cw(c106.222,20.04) 106.4,19.9 ccw(c106.578,19.76) 106.718,19.582 cw(c106.858,19.404) 107.036,19.264 ccw(c107.214,19.123) 107.354,18.946 cw(c107.495,18.768) 107.673,18.627 ccw(c107.85,18.487) 107.991,18.309 cw(c108.131,18.131) 108.309,17.991 ccw(c108.487,17.851) 108.627,17.673 cw(c108.768,17.495) 108.945,17.355 ccw(c109.123,17.214) 109.264,17.036 cw(c109.404,16.859) 109.582,16.718 ccw(c109.76,16.578) 109.9,16.4 110.193,16.107 117.921,16.107 v1(117.974,16.053)
TX1D10: U8.H1 U12-1.31 | length 69.1
  Top Layer w0.15: U8.H1@76,43 81.8,43 81.939,42.861 ccw(c82.094,43.017) 82.25,42.861 82.324,42.935 cw(c82.48,42.78) 82.635,42.935 82.713,42.857 cw(c82.557,42.702) 82.713,42.546 82.483,42.317 82.254,42.087 ccw(c82.409,41.931) 82.254,41.776 82.332,41.698 ccw(c82.487,41.854) 82.643,41.698 83.102,42.157 cw(c83.257,42.002) 83.413,42.157 83.491,42.08 cw(c83.335,41.924) 83.491,41.768 83.261,41.539 83.032,41.309 ccw(c83.187,41.154) 83.032,40.998 83.109,40.92 ccw(c83.265,41.076) 83.42,40.92 83.88,41.38 cw(c84.035,41.224) 84.191,41.38 84.269,41.302 cw(c84.113,41.146) 84.269,40.991 83.809,40.531 ccw(c83.965,40.376) 83.809,40.22 83.887,40.142 ccw(c84.043,40.298) 84.198,40.142 84.428,40.372 84.658,40.602 cw(c84.813,40.446) 84.969,40.602 85.046,40.524 cw(c84.891,40.368) 85.046,40.213 84.587,39.754 ccw(c84.743,39.598) 84.587,39.442 84.665,39.365 ccw(c84.821,39.52) 84.976,39.365 85.206,39.594 85.435,39.824 cw(c85.591,39.668) 85.746,39.824 85.824,39.746 cw(c85.669,39.591) 85.824,39.435 85.595,39.205 85.365,38.976 ccw(c85.521,38.82) 85.365,38.665 85.443,38.587 ccw(c85.598,38.742) 85.754,38.587 86.213,39.046 cw(c86.369,38.891) 86.524,39.046 86.602,38.968 cw(c86.446,38.813) 86.602,38.657 86.528,38.583 ccw(c86.684,38.428) 86.528,38.272 v1(87.35,37.45) ; v1@87.2,37.45 ccw(c86.838,37.45) 87.094,37.706 ccw(c87.35,37.962) v1@87.35,37.6
  Top Layer w0.2: v4@120.636,17.017 cw(c120.466,16.847) 120.707,16.847 cw(c120.948,16.847) v4@120.778,17.017 ; U12-1.31@120.707,16.638 v4@120.707,17.063
  MidLayer1 w0.15: v1@87.35,37.3 cw(c87.35,36.938) 87.606,37.194 cw(c87.862,37.45) v1@87.5,37.45 ; v1(87.35,37.45) 109.543,15.257 117.709,15.257 117.711,15.258 118.877,15.258 v4(120.707,17.088) ; v4@120.582,17.088 cw(c120.28,17.088) 120.494,16.875 cw(c120.707,16.661) v4@120.707,16.963
TX1D11: U8.E6 U12-1.32 | length 69.5
  Top Layer w0.15: v1@70.55,40.275 cw(c70.55,39.853) 70.849,40.151 cw(c71.147,40.45) v1@70.725,40.45 ; v1(70.55,40.45) U8.E6@71,40 ; v2(117.533,15.682) 117.545,15.682 117.668,15.558 120.761,15.558 120.957,15.754 U12-1.32@120.957,16.063
  MidLayer1 w0.15: v1@70.55,40.275 cw(c70.55,39.853) 70.849,40.151 cw(c71.147,40.45) v1@70.725,40.45 ; v1(70.55,40.45) 71,40 71,39.25 71.25,39 73.15,39 73.45,38.7 74.095,38.7 ccw(c74.095,38.78) 74.175,38.78 cw(c74.395,38.78) 74.395,39 74.505,39 cw(c74.505,38.78) 74.725,38.78 74.725,38.62 ccw(c74.945,38.62) 74.945,38.4 75.055,38.4 ccw(c75.055,38.62) 75.275,38.62 75.275,38.78 cw(c75.495,38.78) 75.495,39 75.605,39 cw(c75.605,38.78) 75.825,38.78 75.825,38.62 ccw(c76.045,38.62) 76.045,38.4 76.155,38.4 ccw(c76.155,38.62) 76.375,38.62 76.375,38.78 cw(c76.595,38.78) 76.595,39 76.705,39 cw(c76.705,38.78) 76.925,38.78 76.925,38.62 ccw(c77.145,38.62) 77.145,38.4 77.255,38.4 ccw(c77.255,38.62) 77.475,38.62 77.475,38.78 cw(c77.695,38.78) 77.695,39 77.805,39 cw(c77.805,38.78) 78.025,38.78 78.025,38.62 ccw(c78.245,38.62) 78.245,38.4 78.355,38.4 ccw(c78.355,38.62) 78.575,38.62 78.575,38.78 cw(c78.795,38.78) 78.795,39 78.905,39 cw(c78.905,38.78) 79.125,38.78 79.125,38.62 ccw(c79.345,38.62) 79.345,38.4 79.455,38.4 ccw(c79.455,38.62) 79.675,38.62 79.675,38.78 cw(c79.895,38.78) 79.895,39 80.005,39 cw(c80.005,38.78) 80.225,38.78 80.225,38.62 ccw(c80.445,38.62) 80.445,38.4 80.555,38.4 ccw(c80.555,38.62) 80.775,38.62 80.775,38.78 cw(c80.995,38.78) 80.995,39 81.105,39 cw(c81.105,38.78) 81.325,38.78 ccw(c81.405,38.78) 81.405,38.7 86.75,38.7 109.768,15.682 v2(117.533,15.682) ; v2@117.409,15.558 ccw(c117.111,15.259) 117.111,15.682 ccw(c117.111,16.104) v2@117.409,15.805
TX1EN: U8.G1 U12-1.66 | length 69.5
  Top Layer w0.15: U8.G1@76,42 78.75,42 79.15,41.6 81.15,41.6 85.7,37.05 v1(86.15,37.05) ; v1@86.044,36.944 ccw(c85.788,36.688) 85.788,37.05 ccw(c85.788,37.412) v1@86.044,37.156
  Top Layer w0.2: v4@127.282,18.638 U12-1.66@127.707,18.638 ; v4@127.328,18.567 cw(c127.498,18.397) 127.498,18.638 cw(c127.498,18.879) v4@127.328,18.709
  MidLayer1 w0.15: v1(86.15,37.05) 86.5,37.05 ; v1@86.259,36.947 cw(c86.5,36.717) 86.5,37.05 ; v1@86.259,37.153 ccw(c86.5,37.383) 86.5,37.05 ; v4@127.257,18.513 cw(c127.257,18.138) 127.522,18.403 ; v4(127.257,18.638) 127.287,18.638 127.632,18.293 127.632,15.382 127.008,14.758 117.918,14.758 117.333,14.173 109.377,14.173 86.5,37.05 ; v4@127.382,18.638 ccw(c127.611,18.638) 127.449,18.476
TX1IQSEL: U8.H6 U12-1.20 | length 69.1
  Top Layer w0.15: v1(70.5,42.5) U8.H6@71,43 ; v1@70.5,42.675 ccw(c70.5,43.097) 70.799,42.799 ccw(c71.097,42.5) v1@70.675,42.5
  Top Layer w0.2: U12-1.20@120.207,19.138 v4@120.632,19.138 ; v4@120.586,19.067 ccw(c120.416,18.897) 120.416,19.138 ccw(c120.416,19.379) v4@120.586,19.209
  Bottom Layer w0.15: v1(70.5,42.5) 71.025,43.025 77.971,43.025 81.196,39.8 94.35,39.8 96.359,37.791 cw(c96.465,37.685) 96.571,37.791 96.677,37.685 cw(c96.571,37.579) 96.677,37.473 ccw(c96.783,37.367) 96.677,37.261 96.783,37.155 ccw(c96.889,37.261) 96.995,37.155 cw(c97.102,37.048) 97.208,37.155 97.314,37.048 cw(c97.208,36.942) 97.314,36.836 ccw(c97.42,36.73) 97.314,36.624 97.42,36.518 ccw(c97.526,36.624) 97.632,36.518 cw(c97.738,36.412) 97.844,36.518 97.95,36.412 cw(c97.844,36.306) 97.95,36.2 ccw(c98.056,36.094) 97.95,35.988 98.056,35.882 ccw(c98.162,35.988) 98.268,35.882 cw(c98.374,35.776) 98.48,35.882 98.586,35.776 cw(c98.48,35.67) 98.586,35.564 ccw(c98.693,35.457) 98.586,35.351 98.693,35.245 ccw(c98.799,35.351) 98.905,35.245 cw(c99.011,35.139) 99.117,35.245 99.223,35.139 cw(c99.117,35.033) 99.223,34.927 ccw(c99.329,34.821) 99.223,34.715 99.329,34.609 ccw(c99.435,34.715) 99.541,34.609 cw(c99.647,34.503) 99.753,34.609 99.859,34.503 cw(c99.753,34.397) 99.859,34.291 ccw(c99.965,34.185) 99.859,34.079 99.965,33.973 ccw(c100.071,34.079) 100.177,33.973 cw(c100.284,33.866) 100.39,33.973 100.496,33.866 cw(c100.39,33.76) 100.496,33.654 ccw(c100.602,33.548) 100.496,33.442 100.602,33.336 ccw(c100.708,33.442) 100.814,33.336 cw(c100.92,33.23) 101.026,33.336 101.132,33.23 cw(c101.026,33.124) 101.132,33.018 ccw(c101.238,32.912) 101.132,32.806 101.238,32.7 ccw(c101.344,32.806) 101.45,32.7 cw(c101.556,32.594) 101.662,32.7 101.768,32.594 cw(c101.662,32.488) 101.768,32.382 ccw(c101.875,32.275) 101.768,32.169 101.875,32.063 ccw(c101.981,32.169) 102.087,32.063 cw(c102.193,31.957) 102.299,32.063 102.405,31.957 cw(c102.299,31.851) 102.405,31.745 ccw(c102.511,31.639) 102.405,31.533 102.511,31.427 ccw(c102.617,31.533) 102.723,31.427 cw(c102.829,31.321) 102.935,31.427 103.041,31.321 cw(c102.935,31.215) 103.041,31.109 ccw(c103.147,31.003) 103.041,30.897 103.147,30.791 ccw(c103.253,30.897) 103.359,30.791 cw(c103.466,30.684) 103.572,30.791 103.678,30.684 cw(c103.572,30.578) 103.678,30.472 ccw(c103.784,30.366) 103.678,30.26 103.784,30.154 ccw(c103.89,30.26) 103.996,30.154 cw(c104.102,30.048) 104.208,30.154 104.314,30.048 cw(c104.208,29.942) 104.314,29.836 ccw(c104.42,29.73) 104.314,29.624 104.42,29.518 ccw(c104.526,29.624) 104.632,29.518 cw(c104.738,29.412) 104.844,29.518 104.95,29.412 cw(c104.844,29.306) 104.95,29.2 ccw(c105.056,29.094) 104.95,28.987 105.056,28.881 ccw(c105.163,28.987) 105.269,28.881 cw(c105.375,28.775) 105.481,28.881 105.587,28.775 cw(c105.481,28.669) 105.587,28.563 ccw(c105.693,28.457) 105.587,28.351 105.693,28.245 ccw(c105.799,28.351) 105.905,28.245 cw(c106.011,28.139) 106.117,28.245 106.223,28.139 cw(c106.117,28.033) 106.223,27.927 114.692,19.458 115.427,19.458 115.44,19.472 115.7,19.472 116.211,18.96 118.411,18.96 118.771,19.32 120.445,19.32 ; v1@70.5,42.675 ccw(c70.5,43.097) 70.799,42.799 ccw(c71.097,42.5) v1@70.675,42.5 ; 120.465,19.3 cw(c120.303,19.138) v4@120.532,19.138 ; v4@120.634,19.261 cw(c120.596,19.472) 120.445,19.32 ; v4(120.657,19.138) 120.627,19.138 120.445,19.32
TX2CLK: R154-2.2 R155-2.2 U5.13 U8.M3 U12-2.19 | length 97.1
  Top Layer w0.15: v1@73.55,47.25 cw(c73.55,46.766) U8.M3@73.892,47.108 ; v1(73.55,47.4) 73.55,47.45 U8.M3@74,47 ; v1@73.7,47.4 ccw(c73.941,47.4) 73.77,47.23 ; v1@81.594,63.331 ccw(c81.217,63.708) 81.75,63.708 ; v1(81.7,63.225) v1@81.75,63.275 ; 81.75,63.45 U5.13@81.75,64.175 ; 81.75,63.466 ccw(c81.941,63.466) v1@81.806,63.331 ; v1(115.2,67.85) R154-2.2@116.15,67.85 R155-2.2@117.5,67.85 117.9,67.85 118.73,68.68 U12-2.19@119.671,68.68 ; v1@115.306,67.744 cw(c115.562,67.488) 115.562,67.85 cw(c115.562,68.212) v1@115.306,67.956
  Mid-Layer 2 w0.15: v1@73.4,47.4 ccw(c73.038,47.4) 73.294,47.656 ccw(c73.55,47.912) 73.55,47.55 ccw(c73.55,47.913) 73.806,47.656 ; v1(73.55,47.4) 73,47.95 73,49.7 72,50.7 72,53.83 ccw(c71.88,53.83) 71.88,53.95 71.77,53.95 cw(c71.77,54.07) 71.65,54.07 71.65,54.13 cw(c71.77,54.13) 71.77,54.25 72.23,54.25 ccw(c72.23,54.37) 72.35,54.37 72.35,54.43 ccw(c72.23,54.43) 72.23,54.55 71.77,54.55 cw(c71.77,54.67) 71.65,54.67 71.65,54.73 cw(c71.77,54.73) 71.77,54.85 72.23,54.85 ccw(c72.23,54.97) 72.35,54.97 72.35,55.03 ccw(c72.23,55.03) 72.23,55.15 72.12,55.15 cw(c72.12,55.27) 72,55.27 72,55.75 79.475,63.225 81.525,63.225 v1@81.7,63.4 ; v1@73.55,50.35 cw(c73.55,49.988) 73.806,50.244 cw(c74.062,50.5) v1@73.7,50.5 ; v1(73.55,50.5) 74,50.05 74,47.85 v1(73.55,47.4) ; v1@73.7,47.4 cw(c74.061,47.4) 73.806,47.655 ; v1@81.594,63.119 ccw(c81.338,62.863) 81.338,63.225 ccw(c81.338,63.587) v1@81.594,63.331
  Bottom Layer w0.15: v1(73.55,50.5) 87.4,50.5 88.55,51.65 90.85,51.65 91.1,51.9 cw(c91.259,52.059) 91.418,52.218 ccw(c91.577,52.377) 91.736,52.536 cw(c91.895,52.695) 92.055,52.855 ccw(c92.214,53.014) 92.373,53.173 cw(c92.532,53.332) 92.691,53.491 ccw(c92.85,53.65) 93.009,53.809 cw(c93.168,53.968) 93.327,54.127 ccw(c93.486,54.286) 93.646,54.446 cw(c93.805,54.605) 93.964,54.764 ccw(c94.123,54.923) 94.282,55.082 cw(c94.441,55.241) 94.6,55.4 ccw(c94.759,55.559) 94.918,55.718 cw(c95.077,55.877) 95.237,56.037 ccw(c95.396,56.196) 95.555,56.355 cw(c95.714,56.514) 95.873,56.673 ccw(c96.032,56.832) 96.191,56.991 cw(c96.35,57.15) 96.509,57.309 ccw(c96.668,57.468) 96.828,57.628 cw(c96.987,57.787) 97.146,57.946 ccw(c97.305,58.105) 97.464,58.264 cw(c97.623,58.423) 97.782,58.582 ccw(c97.941,58.741) 98.1,58.9 cw(c98.259,59.059) 98.419,59.219 ccw(c98.578,59.378) 98.737,59.537 cw(c98.896,59.696) 99.055,59.855 ccw(c99.214,60.014) 99.373,60.173 cw(c99.532,60.332) 99.691,60.491 ccw(c99.85,60.65) 100.01,60.81 cw(c100.169,60.969) 100.328,61.128 ccw(c100.487,61.287) 100.646,61.446 cw(c100.805,61.605) 100.964,61.764 ccw(c101.123,61.923) 101.282,62.082 cw(c101.441,62.241) 101.601,62.401 ccw(c101.76,62.56) 101.919,62.719 cw(c102.078,62.878) 102.237,63.037 ccw(c102.381,63.211) 102.555,63.355 107.05,67.85 v1(115.2,67.85) ; v1@73.656,50.394 cw(c73.912,50.138) 73.912,50.5 cw(c73.912,50.862) v1@73.656,50.606 ; v1@115.094,67.744 ccw(c114.838,67.488) 114.838,67.85 ccw(c114.838,68.212) v1@115.094,67.956
TX2D0: U8.R3 U12-2.21 | length 69
  Top Layer w0.15: U8.R3@74,50 74.5,50.5 86.35,50.5 v1(87.6,51.75) ; v1@87.45,51.75 cw(c87.088,51.75) 87.344,51.494 cw(c87.6,51.238) v1@87.6,51.6 ; v1(119.1,68.15) 119.062,68.15 v1@119.032,68.18 ; v1@119.206,68.044 cw(c119.534,67.716) U12-2.21@119.534,68.18 ; v1@119.206,68.256 ccw(c119.39,68.44) 119.39,68.18 ; U12-2.21@119.671,68.18 v1@119.032,68.18 ; v1@119.032,68.18 119.03,68.18 119,68.15 119,68.2 119,68.212 v1@119.032,68.18
  MidLayer1 w0.15: v1(87.6,51.75) 88.05,51.75 88.85,52.55 90.25,52.55 90.539,52.839 ccw(c90.419,52.959) 90.539,53.079 cw(c90.666,53.207) 90.539,53.334 90.603,53.398 cw(c90.73,53.27) 90.857,53.398 90.977,53.277 91.098,53.157 ccw(c91.225,53.284) 91.352,53.157 91.416,53.221 ccw(c91.288,53.348) 91.416,53.475 91.175,53.716 cw(c91.303,53.843) 91.175,53.97 91.239,54.034 cw(c91.366,53.907) 91.493,54.034 91.614,53.914 91.734,53.793 ccw(c91.861,53.921) 91.988,53.793 92.052,53.857 ccw(c91.925,53.984) 92.052,54.112 91.932,54.232 91.812,54.352 cw(c91.939,54.479) 91.812,54.607 91.875,54.67 cw(c92.003,54.543) 92.13,54.67 92.25,54.55 92.37,54.43 ccw(c92.498,54.557) 92.625,54.43 92.688,54.494 ccw(c92.561,54.621) 92.688,54.748 92.568,54.868 92.448,54.988 cw(c92.575,55.116) 92.448,55.243 92.512,55.307 cw(c92.639,55.179) 92.766,55.307 93.007,55.066 ccw(c93.134,55.194) 93.261,55.066 93.325,55.13 ccw(c93.198,55.257) 93.325,55.384 93.205,55.505 93.084,55.625 cw(c93.212,55.752) 93.084,55.879 93.148,55.943 cw(c93.275,55.816) 93.403,55.943 93.643,55.703 ccw(c93.77,55.83) 93.898,55.703 93.961,55.766 ccw(c93.834,55.894) 93.961,56.021 93.841,56.141 93.721,56.261 cw(c93.848,56.389) 93.721,56.516 93.785,56.579 cw(c93.912,56.452) 94.039,56.579 94.159,56.459 94.279,56.339 ccw(c94.407,56.466) 94.534,56.339 94.598,56.403 ccw(c94.47,56.53) 94.598,56.657 94.477,56.777 94.357,56.898 cw(c94.485,57.025) 94.357,57.152 94.421,57.216 cw(c94.548,57.089) 94.675,57.216 94.796,57.096 94.916,56.975 ccw(c95.043,57.103) 95.17,56.975 95.234,57.039 ccw(c95.107,57.166) 95.234,57.294 94.994,57.534 cw(c95.121,57.661) 94.994,57.789 95.057,57.852 cw(c95.185,57.725) 95.312,57.852 95.432,57.732 95.552,57.612 ccw(c95.68,57.739) 95.807,57.612 95.87,57.675 ccw(c95.743,57.803) 95.87,57.93 95.63,58.17 cw(c95.757,58.298) 95.63,58.425 95.694,58.489 cw(c95.821,58.361) 95.948,58.489 96.068,58.368 96.189,58.248 ccw(c96.316,58.376) 96.443,58.248 96.507,58.312 ccw(c96.38,58.439) 96.507,58.566 96.387,58.687 96.266,58.807 cw(c96.394,58.934) 96.266,59.061 96.33,59.125 cw(c96.457,58.998) 96.585,59.125 96.705,59.005 96.825,58.885 ccw(c96.952,59.012) 97.08,58.885 97.143,58.948 ccw(c97.016,59.076) 97.143,59.203 97.023,59.323 96.903,59.443 cw(c97.03,59.571) 96.903,59.698 96.966,59.761 cw(c97.094,59.634) 97.221,59.761 97.461,59.521 ccw(c97.589,59.648) 97.716,59.521 97.78,59.585 ccw(c97.652,59.712) 97.78,59.839 97.659,59.959 97.539,60.08 cw(c97.667,60.207) 97.539,60.334 97.603,60.398 cw(c97.73,60.271) 97.857,60.398 98.098,60.157 ccw(c98.225,60.285) 98.352,60.157 98.416,60.221 ccw(c98.289,60.348) 98.416,60.476 98.296,60.596 105.95,68.25 115.466,68.25 115.566,68.15 119,68.15 119,68.212 119.062,68.15 v1(119.1,68.15) ; v1@87.706,51.644 cw(c87.962,51.388) 87.962,51.75 cw(c87.962,52.112) v1@87.706,51.856 ; 118.738,68.15 ccw(c118.738,68.512) v1@118.994,68.256 ; 118.738,68.15 cw(c118.738,67.788) v1@118.994,68.044
TX2D1: U8.L4 U12-2.22 | length 68.8
  Top Layer w0.15: v1@72.5,46.325 cw(c72.5,45.903) 72.799,46.201 cw(c73.097,46.5) v1@72.675,46.5 ; v1(72.5,46.5) U8.L4@73,46
  Top Layer w0.2: U12-2.22@120.246,67.93 v4@120.671,67.93 ; v4@120.625,67.859 ccw(c120.455,67.688) 120.455,67.93 ccw(c120.455,68.171) v4@120.625,68.001
  Bottom Layer w0.15: v1(72.5,46.5) 72.95,46.95 88.7,46.95 89.862,48.112 cw(c89.933,48.183) 89.862,48.254 89.968,48.36 cw(c90.039,48.289) 90.11,48.36 ccw(c90.18,48.43) 90.251,48.36 90.357,48.466 ccw(c90.286,48.536) 90.357,48.607 cw(c90.428,48.678) 90.357,48.749 ; v1@72.5,46.675 ccw(c72.5,47.097) 72.799,46.799 ccw(c73.097,46.5) v1@72.675,46.5 ; 90.357,48.749 90.463,48.855 cw(c90.534,48.784) 90.605,48.855 ccw(c90.675,48.925) 90.746,48.855 90.852,48.961 ccw(c90.781,49.031) 90.852,49.102 cw(c90.923,49.173) 90.852,49.244 90.958,49.35 cw(c91.029,49.279) 91.1,49.35 ccw(c91.17,49.42) 91.241,49.35 91.347,49.456 ccw(c91.276,49.526) 91.347,49.597 cw(c91.418,49.668) 91.347,49.739 91.453,49.845 cw(c91.524,49.774) 91.595,49.845 ccw(c91.665,49.915) 91.736,49.845 91.842,49.951 ccw(c91.771,50.021) 91.842,50.092 cw(c91.913,50.163) 91.842,50.234 91.948,50.34 cw(c92.019,50.269) 92.09,50.34 ccw(c92.16,50.41) 92.231,50.34 92.337,50.446 ccw(c92.266,50.516) 92.337,50.587 cw(c92.408,50.658) 92.337,50.729 92.443,50.835 cw(c92.514,50.764) 92.585,50.835 ccw(c92.655,50.905) 92.726,50.835 92.832,50.941 ccw(c92.761,51.011) 92.832,51.082 cw(c92.903,51.153) 92.832,51.223 92.938,51.33 cw(c93.009,51.259) 93.08,51.33 ccw(c93.15,51.4) 93.221,51.33 93.327,51.436 ccw(c93.256,51.506) 93.327,51.577 cw(c93.398,51.648) 93.327,51.718 93.433,51.825 cw(c93.504,51.754) 93.575,51.825 ccw(c93.645,51.895) 93.716,51.825 93.822,51.931 ccw(c93.751,52.001) 93.822,52.072 cw(c93.893,52.143) 93.822,52.213 93.928,52.32 cw(c93.999,52.249) 94.07,52.32 ccw(c94.14,52.39) 94.211,52.319 94.317,52.426 ccw(c94.246,52.496) 94.317,52.567 cw(c94.388,52.638) 94.317,52.708 94.423,52.814 cw(c94.494,52.744) 94.564,52.814 ccw(c94.635,52.885) 94.706,52.814 94.812,52.921 ccw(c94.741,52.991) 94.812,53.062 cw(c94.883,53.133) 94.812,53.203 94.918,53.309 cw(c94.989,53.239) 95.059,53.309 ccw(c95.13,53.38) 95.201,53.309 95.307,53.416 ccw(c95.236,53.486) 95.307,53.557 cw(c95.378,53.628) 95.307,53.698 95.413,53.804 cw(c95.484,53.734) 95.554,53.804 ccw(c95.625,53.875) 95.696,53.804 95.802,53.91 ccw(c95.731,53.981) 95.802,54.052 cw(c95.873,54.123) 95.802,54.193 95.908,54.299 cw(c95.979,54.229) 96.049,54.299 ccw(c96.12,54.37) 96.191,54.299 96.297,54.405 ccw(c96.226,54.476) 96.297,54.547 cw(c96.368,54.618) 96.297,54.688 96.403,54.794 cw(c96.474,54.724) 96.544,54.794 ccw(c96.615,54.865) 96.686,54.794 96.792,54.9 ccw(c96.721,54.971) 96.792,55.042 cw(c96.863,55.113) 96.792,55.183 96.898,55.289 cw(c96.969,55.219) 97.039,55.289 ccw(c97.11,55.36) 97.181,55.289 97.287,55.395 ccw(c97.216,55.466) 97.287,55.537 cw(c97.358,55.608) 97.287,55.678 97.393,55.784 cw(c97.464,55.714) 97.534,55.784 ccw(c97.605,55.855) 97.676,55.784 97.782,55.89 ccw(c97.711,55.961) 97.782,56.032 cw(c97.853,56.103) 97.782,56.173 97.888,56.279 cw(c97.959,56.209) 98.029,56.279 ccw(c98.1,56.35) 98.171,56.279 98.277,56.385 ccw(c98.206,56.456) 98.277,56.527 cw(c98.347,56.597) 98.277,56.668 98.383,56.774 cw(c98.454,56.704) 98.524,56.774 ccw(c98.595,56.845) 98.666,56.774 98.772,56.88 ccw(c98.701,56.951) 98.772,57.022 cw(c98.842,57.092) 98.772,57.163 98.878,57.269 cw(c98.949,57.199) 99.019,57.269 ccw(c99.09,57.34) 99.161,57.269 99.267,57.375 ccw(c99.196,57.446) 99.267,57.517 cw(c99.337,57.587) 99.267,57.658 99.373,57.764 cw(c99.444,57.694) 99.514,57.764 ccw(c99.585,57.835) 99.656,57.764 99.762,57.87 ccw(c99.691,57.941) 99.762,58.012 cw(c99.832,58.082) 99.762,58.153 99.868,58.259 cw(c99.938,58.188) 100.009,58.259 ccw(c100.08,58.33) 100.151,58.259 100.257,58.365 ccw(c100.186,58.436) 100.257,58.507 cw(c100.327,58.577) 100.257,58.648 100.363,58.754 cw(c100.433,58.683) 100.504,58.754 ccw(c100.575,58.825) 100.646,58.754 100.752,58.86 ccw(c100.681,58.931) 100.752,59.002 cw(c100.822,59.072) 100.752,59.143 100.858,59.249 cw(c100.928,59.178) 100.999,59.249 ccw(c101.07,59.32) 101.141,59.249 101.247,59.355 ccw(c101.176,59.426) 101.247,59.497 cw(c101.317,59.567) 101.247,59.638 101.353,59.744 cw(c101.423,59.673) 101.494,59.744 ccw(c101.565,59.815) 101.636,59.744 101.742,59.85 ccw(c101.671,59.921) 101.742,59.992 cw(c101.812,60.062) 101.742,60.133 101.848,60.239 cw(c101.918,60.168) 101.989,60.239 ccw(c102.06,60.31) 102.13,60.239 102.237,60.345 ccw(c102.166,60.416) 102.237,60.487 cw(c102.307,60.557) 102.237,60.628 102.343,60.734 cw(c102.413,60.663) 102.484,60.734 ccw(c102.555,60.805) 102.625,60.734 102.732,60.84 ccw(c102.661,60.911) 102.732,60.982 cw(c102.802,61.052) 102.732,61.123 102.838,61.229 cw(c102.908,61.158) 102.979,61.229 ccw(c103.05,61.3) 103.12,61.229 103.227,61.335 ccw(c103.156,61.406) 103.227,61.477 cw(c103.297,61.547) 103.226,61.618 103.333,61.724 cw(c103.403,61.653) 103.474,61.724 ccw(c103.545,61.795) 103.615,61.724 103.721,61.83 ccw(c103.651,61.901) 103.721,61.971 cw(c103.792,62.042) 103.721,62.113 103.828,62.219 cw(c103.898,62.148) 103.969,62.219 ccw(c104.04,62.29) 104.11,62.219 104.216,62.325 ccw(c104.146,62.396) 104.216,62.466 cw(c104.287,62.537) 104.216,62.608 104.323,62.714 cw(c104.393,62.643) 104.464,62.714 ccw(c104.535,62.785) 104.605,62.714 104.711,62.82 ccw(c104.641,62.891) 104.711,62.961 cw(c104.782,63.032) 104.711,63.103 ; 104.711,63.103 104.818,63.209 cw(c104.888,63.138) 104.959,63.209 ccw(c105.03,63.28) 105.1,63.209 105.206,63.315 ccw(c105.136,63.386) 105.206,63.456 cw(c105.277,63.527) 105.206,63.598 105.312,63.704 cw(c105.383,63.633) 105.454,63.704 ccw(c105.525,63.775) 105.595,63.704 105.701,63.81 ccw(c105.631,63.881) 105.701,63.951 cw(c105.772,64.022) 105.701,64.093 105.807,64.199 cw(c105.878,64.128) 105.949,64.199 ccw(c106.02,64.27) 106.09,64.199 ; 106.09,64.199 106.196,64.305 ccw(c106.126,64.376) 106.196,64.446 cw(c106.267,64.517) 106.196,64.588 106.302,64.694 cw(c106.373,64.623) 106.444,64.694 ccw(c106.515,64.765) 106.585,64.694 ; 106.585,64.694 106.691,64.8 ccw(c106.621,64.871) 106.691,64.941 cw(c106.762,65.012) 106.691,65.083 106.797,65.189 cw(c106.868,65.118) 106.939,65.189 ccw(c107.01,65.26) 107.08,65.189 107.186,65.295 ccw(c107.116,65.366) 107.186,65.436 cw(c107.257,65.507) 107.186,65.578 107.292,65.684 cw(c107.363,65.613) 107.434,65.684 ccw(c107.505,65.755) 107.575,65.684 107.681,65.79 ccw(c107.611,65.861) 107.681,65.931 cw(c107.752,66.002) 107.681,66.073 ; 107.681,66.073 107.787,66.179 ; 107.787,66.179 cw(c107.858,66.108) 107.929,66.179 ccw(c107.999,66.249) 108.07,66.179 108.176,66.285 ccw(c108.106,66.356) 108.176,66.426 108.4,66.65 117.05,66.65 117.7,67.3 118.837,67.3 119.467,67.93 v4(120.696,67.93) ; v4@120.608,67.841 ccw(c120.394,67.628) 120.394,67.93 ccw(c120.394,68.232) v4@120.608,68.018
